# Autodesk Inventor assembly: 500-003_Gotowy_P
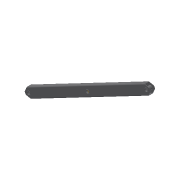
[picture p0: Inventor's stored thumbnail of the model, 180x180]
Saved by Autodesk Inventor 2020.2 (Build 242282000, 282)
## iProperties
Created: 2016-09
Part Number: 500-003_Gotowy_P
Document SubType Name: Assembly
Designer: F.Stasiak
Description: Ramie pojedyncze
Manager: www.cadconsulting.pl
Company: Fabian Stasiak CAD Consulting
Author: F.Stasiak
Subject: Zbiór ćwiczeń. Autodesk Inventor 2020. Kurs podstawowy
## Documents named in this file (3)
- C:\2020_Kurs_podstawowy\R6 Zespoły\Warsztat\Komponenty\500-003_Gotowy_P.iam
- C:\2020_Kurs_podstawowy\R6 Zespoły\Warsztat\Komponenty\DIN 59 410 - 500-04-01.ipt
- C:\2020_Kurs_podstawowy\R6 Zespoły\Warsztat\Komponenty\500-03-02.ipt
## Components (4 placed, 2 different names)
1. DIN 59 410 - 500-04-01:1
2. 500-03-02:1
3. 500-03-02:2
4. 500-03-02:3
